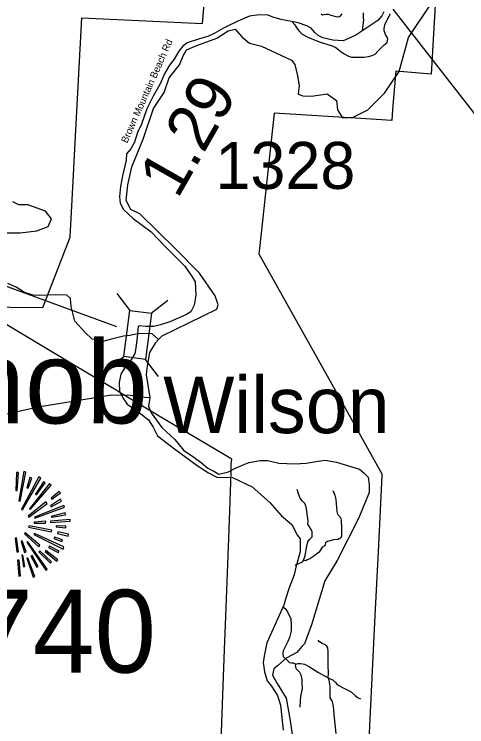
# Model space of a CAD drawing. Extents: x 1159738 to 1321356, y 736314 to 882035.
# Drawn here: x 1180449 to 1185260, y 816118 to 823694 of the extents above; entities that cross this region are included whole.
import ezdxf

# ---------------------------------------------------------------- set-up
doc = ezdxf.new("R2010")
doc.units = 0
for name, color, linetype in [('Exist Boundary Land Use Forest National US Forest Service', 7, 'Continuous'), ('Exist Geographical Mountain Summit CELL', 7, 'Continuous'), ('Exist Geographical Mountain Summit Elevation Number Label', 7, 'Continuous'), ('Exist Geographical Mountain Summit Label', 7, 'Continuous'), ('Exist Hydrographic Creek Single Shore', 7, 'Continuous'), ('Exist Hydrographic Creek Single Shore Label', 7, 'Continuous'), ('Exist Road Non-System Type 51', 7, 'Continuous'), ('Exist Road Secondary Mileage Hundredths English Label', 7, 'Continuous'), ('Exist Road Secondary Structure Standard Bridge CELL', 7, 'Continuous'), ('Exist Road Secondary Structure Standard Bridge Number Label', 7, 'Continuous'), ('Exist Road Secondary Type 41 Attributed', 7, 'Continuous'), ('Exist Road Secondary Type 51 Label', 7, 'Continuous'), ('Exist Road Secondary Type 51 Number Label', 7, 'Continuous')]:
    doc.layers.add(name, color=color, linetype=linetype)

msp = doc.modelspace()

# ---------------------------------------------------------------- linework, layer by layer
at = {"layer": 'Exist Boundary Land Use Forest National US Forest Service'}
for points in [[(1181077.2, 821985.4), (1181096, 822331.8), (1181167.4, 823654.7), (1182450.4, 823595.7), (1182625.4, 825621.8), (1181994.3, 825639.1), (1181234.4, 825659.8), (1181255.3, 826054.8), (1181338.3, 827288.9), (1181518.2, 827293.9), (1181553.8, 828399.8), (1181557.3, 828511.9), (1181490.6, 828516.2), (1181211.2, 828534.3), (1180846.2, 828557.9), (1180845.6, 828555), (1180799.3, 828350.9), (1180737.3, 828248.9), (1180670.2, 828186.9), (1180611.3, 828143.9), (1180560.2, 828127.9), (1180461.3, 828103.9), (1180360.3, 828086.9)], [(1184945.2, 824175.1), (1184917, 823671.3), (1184882.5, 823056.8), (1184504.5, 823087.8), (1184471.8, 822681), (1184462.5, 822564.7), (1184077.2, 822588.5), (1184012.8, 822592.5), (1183957.3, 822595.9), (1183213.5, 822641.7), (1183054.5, 821201.7), (1183047.5, 821147.7), (1183972.5, 819495.7), (1184187.7, 819111.4), (1184357.7, 818807.6), (1184356.6, 818788), (1184316.2, 817978), (1184282.6, 817301.6), (1184211.7, 815834.6)], [(1182508.3, 815466.3), (1182522.7, 815466.5), (1182640.7, 815773.5), (1182683.7, 816938.3), (1182693.7, 817202.6), (1182732, 818216.6), (1182751, 818718.3), (1182755.5, 818839.6), (1182753.5, 818911.6), (1182761.5, 818961.6), (1181970.5, 819431.6), (1181864.5, 819494.6), (1181563.8, 819677.1), (1181538, 819692.8), (1181497.4, 819717.4), (1181490.5, 819721.6), (1181079, 819966.9), (1180046.5, 820582.6), (1180752.5, 820574.6), (1180798.9, 820694.6), (1181041.5, 821322.7), (1181077.2, 821985.4)]]:
    msp.add_lwpolyline(points, dxfattribs=at)
at = {"layer": 'Exist Geographical Mountain Summit CELL'}
for points in [[(1180464, 818631.8), (1180479.7, 818631.8), (1180494.3, 818820.7), (1180472.5, 818820.7)], [(1180511.9, 818518.2), (1180571.5, 818826.4), (1180549.6, 818833.6), (1180498.8, 818521.2)], [(1180524.9, 818431.1), (1180536.6, 818423.8), (1180731.2, 818762.3), (1180709.4, 818777.1)], [(1180582.9, 818659.2), (1180596.2, 818654.7), (1180634, 818762.3), (1180615.1, 818769.5)], [(1180609.1, 818436.8), (1180618, 818428.2), (1180840.3, 818685.3), (1180824.3, 818704.3)], [(1180758.9, 818723.3), (1180674.7, 818589.5), (1180686.4, 818585), (1180776.2, 818710.3)], [(1180840.3, 818548.8), (1180847.7, 818538.7), (1180939.2, 818603.9), (1180924.6, 818618.5)], [(1180840.3, 818457.3), (1180950.7, 818516.9), (1180939.2, 818537.1), (1180834.7, 818467.4)], [(1180596.2, 818356.9), (1180603.4, 818346.8), (1180798, 818490.6), (1180785.2, 818508.1)], [(1180664.3, 818345.3), (1180668.7, 818336.4), (1180981.3, 818451.2), (1180974.1, 818470.1)], [(1180847.7, 818345.3), (1180994.6, 818371.5), (1180988.7, 818393.2), (1180841.9, 818354.2)], [(1180660.3, 818294.6), (1180660.3, 818282.9), (1180780.7, 818282.9), (1180783.6, 818303.1)], [(1180833.1, 818290.1), (1181042.5, 818303.1), (1181043.8, 818322), (1180834.7, 818303.1)], [(1180601.8, 818239.3), (1180844.8, 818191.4), (1180849.1, 818208.7), (1180606.3, 818253.7)], [(1180892.7, 818242.2), (1180998.7, 818233.2), (1180998.7, 818250.7), (1180894.3, 818255)], [(1180557.1, 818170.9), (1180711, 818029.8), (1180721.1, 818047.2), (1180564.3, 818179.7)], [(1180657, 818160.8), (1180969.8, 818008), (1180977, 818029.8), (1180663.1, 818172.3)], [(1180870.9, 818120.1), (1180955.2, 818087.9), (1180962.4, 818105.5), (1180876.7, 818132.9)], [(1180908.9, 818173.6), (1181022, 818144.6), (1181024.9, 818166.4), (1180912.9, 818191.4)], [(1180459.5, 818124.4), (1180475.4, 817976.3), (1180493, 817977.4), (1180472.5, 818127.3)], [(1180523.6, 818089.5), (1180558.4, 817970.2), (1180574.4, 817977.4), (1180532.1, 818093.8)], [(1180581.6, 818080.5), (1180783.6, 817781.3), (1180798, 817792.8), (1180591.7, 818085)], [(1180711, 817977.4), (1180831.5, 817861.1), (1180844.8, 817871.5), (1180719.8, 817987.5)], [(1180777.8, 817980.3), (1180899.9, 817877.1), (1180912.9, 817891.7), (1180785.2, 817990.7)], [(1180814.2, 818024.2), (1180914.5, 817971.8), (1180924.6, 817986.3), (1180823, 818039.9)], [(1180562.7, 817823.4), (1180540.9, 817942.8), (1180527.8, 817942.8), (1180545.4, 817819.1)], [(1180581.6, 817909.3), (1180651.4, 817710), (1180668.7, 817717.2), (1180593.3, 817912.2)], [(1180623.6, 817932.4), (1180687.6, 817814.6), (1180703.8, 817823.4), (1180638.5, 817938.3)], [(1180484.2, 817890.4), (1180498.8, 817720.4), (1180514.8, 817724.4), (1180501.5, 817890.4)]]:
    msp.add_lwpolyline(points, close=True, dxfattribs=at)
at = {"layer": 'Exist Hydrographic Creek Single Shore'}
for points in [[(1181983.1, 820235), (1182020.2, 820275), (1182601.5, 820558.9), (1182616.9, 820602.5), (1182583.6, 820699.9), (1182419.6, 820940.9), (1182164.4, 821201), (1181782.2, 821570.3), (1181687.4, 821619), (1181638.7, 821713.8), (1181656.6, 821879.6), (1181697.5, 822071.9), (1181820.5, 822366.7), (1181930, 822691.2), (1182042.7, 822860.4), (1182094, 823019.3), (1182206.7, 823157.8), (1182245.1, 823250.1), (1182281, 823316.7), (1182388.6, 823362.9), (1182601.2, 823439.8), (1182721.6, 823519.2), (1182798.5, 823534.6), (1182872.8, 823450), (1182949.6, 823385.9), (1183077.7, 823355.2), (1183395, 823206.7), (1183430.8, 823158), (1183461.6, 823040.1), (1183479.5, 822937.5), (1183466.7, 822845.2), (1183515.4, 822827.3), (1183610.2, 822822.2), (1183776.7, 822847.8), (1183874.1, 822778.6), (1183884.3, 822676), (1183938.1, 822594), (1184050.8, 822599.1), (1184209.7, 822676), (1184383.9, 822855.5), (1184542.7, 823086.2), (1184640.4, 823447.1), (1184884.4, 823813.2)], [(1180362.1, 821368.9), (1180513.2, 821368.9), (1180687.4, 821391.9), (1180810.4, 821435.5), (1180843.7, 821520.1), (1180782.2, 821599.6), (1180592.6, 821666.3), (1180496.3, 821667.7), (1180432.2, 821701)], [(1181759.3, 820296.1), (1181677.9, 820279.1), (1181611.1, 820270.1), (1181467.7, 820236.8), (1181401.1, 820216.3), (1181275.5, 820239.4), (1181203.8, 820308.6), (1181091.1, 820431.6), (1181055.2, 820588), (1181047.5, 820670.1), (1181006.5, 820708.5), (1180886.1, 820711.1), (1180722.2, 820703.4), (1180650.4, 820708.5), (1180558.2, 820734.2), (1180468.5, 820790.6), (1180378.9, 820831.6)], [(1181983.1, 820235), (1181913.6, 820294.4), (1181854.5, 820300.9), (1181759.3, 820296.1)], [(1181983.1, 820235), (1181948, 820198.3), (1181886.5, 820095.7), (1181868.6, 819993.2), (1181858.4, 819931.6), (1181850.7, 819859.9), (1181889.1, 819618.9)], [(1180306.6, 819430.5), (1180701.5, 819521.2), (1181157.3, 819593.9), (1181354.5, 819626.2), (1181480.1, 819647.8), (1181682.5, 819642.6), (1181779.8, 819624.7), (1181889.1, 819618.9)], [(1181889.1, 819618.9), (1181875.4, 819524.8), (1181903.6, 819455.5), (1182018.9, 819299.2), (1182154.6, 819173.5), (1182246.9, 819060.7), (1182359.6, 818983.8), (1182439, 818924.9), (1182508.2, 818868.5), (1182569.7, 818835.1), (1182623.5, 818804.4), (1182725.9, 818830), (1182807.9, 818871), (1182941.2, 818927.4), (1183061.6, 818947.9), (1183141, 818947.9), (1183261.4, 818919.7), (1183433, 818914.6), (1183553.4, 818919.7), (1183679, 818942.8), (1183753.3, 818953.1), (1183876.2, 818932.6), (1184119.6, 818858.2), (1184164.8, 818817.9), (1184210.9, 818771.7), (1184223.7, 818692.2), (1184221.2, 818607.6), (1184111, 818341), (1183880.5, 817885.8), (1183752.4, 817670.5), (1183609.1, 817200.1), (1183534.8, 817000.1), (1183506.7, 816971.9), (1183452.9, 816907.8), (1183340.1, 816848.8), (1183248.5, 816765.6), (1183210.1, 816732.3), (1183194.7, 816668.2), (1183243.4, 816578.5), (1183340.8, 816422.1), (1183381.8, 816186.2), (1183404.8, 816035)]]:
    msp.add_lwpolyline(points, dxfattribs=at)
at = {"layer": 'Exist Road Non-System Type 51'}
for points in [[(1183404.5, 823614.1), (1183431.2, 823579.8), (1183461.7, 823534), (1183486.5, 823505.3), (1183509.4, 823482.4), (1183568.5, 823451.9), (1183702, 823398.5), (1183818.3, 823360.3), (1183866, 823339.3), (1183921.3, 823297.4), (1183955.6, 823272.5), (1184001.4, 823249.6), (1184035.7, 823236.3), (1184100.5, 823238.2), (1184167.3, 823238.2), (1184216.8, 823243.9), (1184255, 823255.4), (1184287.4, 823270.6), (1184316, 823301.2), (1184352.2, 823341.2), (1184382.7, 823368), (1184413.2, 823394.7), (1184417.1, 823411.8), (1184419, 823436.6), (1184394.2, 823478.6), (1184382.7, 823516.8), (1184380.8, 823543.5), (1184390.4, 823579.8), (1184419, 823648.5), (1184449.5, 823700)], [(1183710.4, 823698.2), (1183725.8, 823688.7), (1183740.7, 823691.1), (1183766.3, 823695.9), (1183787.1, 823693.5), (1183813.3, 823685.1), (1183866.3, 823669.7), (1183887.7, 823667.3), (1183905.5, 823669.7), (1183917.7, 823676.2), (1183936.2, 823697.6)], [(1184158, 823709.8), (1184157.4, 823685.4), (1184159.8, 823656.8), (1184163.4, 823632.4), (1184150.3, 823549), (1184149.1, 823517.7)], [(1183436.4, 817835.2), (1183468.7, 817850.6), (1183511.8, 817872.2), (1183524.1, 817884.5), (1183533.3, 817918.3), (1183541, 817939.8), (1183559.4, 818039.8), (1183570.2, 818084.5), (1183587.1, 818110.6), (1183599.4, 818121.4), (1183614.8, 818136.8), (1183617.8, 818153.7), (1183617.8, 818190.6), (1183605.5, 818216.7), (1183588.6, 818244.4), (1183571.7, 818272.1), (1183573.2, 818309.1), (1183551.7, 818456.7), (1183536.4, 818490.6), (1183511.8, 818515.2), (1183488.7, 818547.5), (1183471.8, 818593.6), (1183456.4, 818639.8)], [(1183834.7, 818628.4), (1183857.8, 818579.1), (1183868.6, 818533), (1183877.8, 818405.3), (1183887, 818377.6), (1183917.8, 818343.8), (1183923.9, 818313), (1183928.5, 818225.3), (1183926.9, 818141.2), (1183919.2, 818130.5), (1183910, 818118.2), (1183891.5, 818107.4), (1183846.9, 818104.3), (1183780.8, 818088.9), (1183756.2, 818072), (1183751.6, 818042.8), (1183724, 818025.9), (1183711.7, 818008.9), (1183691.7, 817973.6), (1183633.3, 817932), (1183590.4, 817904.7), (1183562.7, 817892.4), (1183547.3, 817881.6), (1183524.1, 817884.5)], [(1183303, 817392.3), (1183327.6, 817376.9), (1183353.7, 817341.5), (1183389.1, 817264.6), (1183393.7, 817198.4), (1183393.7, 817138.4), (1183375.3, 817067.7), (1183356.8, 817024.6), (1183307.6, 816924.6), (1183303, 816898.5), (1183309.2, 816866.1), (1183350.7, 816824.6), (1183375.2, 816801.9), (1183396.7, 816797.3), (1183415.2, 816797.3), (1183444.4, 816783.4)], [(1183787, 816638), (1183788.6, 816687.3), (1183785.5, 816773.4), (1183785.5, 816914.9), (1183782.4, 816956.5), (1183773.2, 816974.9), (1183754.7, 816990.3), (1183722.5, 817004.2), (1183693.2, 817019.6), (1183679.4, 817038)], [(1183444.4, 816783.4), (1183436.5, 816774.5), (1183438, 816757.6), (1183444.2, 816737.6), (1183482.6, 816699.1), (1183494.9, 816668.3), (1183507.2, 816622.2), (1183505.7, 816576), (1183510.3, 816526.8), (1183501.1, 816489.9), (1183490.3, 816444.2), (1183487.2, 816393.4), (1183485.7, 816325.8)], [(1183444.4, 816783.4), (1183464.2, 816788.8), (1183494.9, 816788.8), (1183534.9, 816784.2), (1183587.2, 816756.5), (1183684, 816696.5), (1183787, 816638), (1183840.8, 816611.9), (1183862.3, 816593.4), (1183886.9, 816564.2), (1183960.7, 816525.7), (1184029.9, 816490.4), (1184072.9, 816451.9), (1184105.2, 816424.2), (1184128.3, 816413.4)], [(1183787, 816638), (1183798, 816593.7), (1183804.2, 816549.1), (1183802.6, 816506.1), (1183804.2, 816449.1), (1183805.7, 816426.1), (1183828.8, 816386.1), (1183838, 816333.8), (1183848.8, 816212.2), (1183867.2, 816047.6)]]:
    msp.add_lwpolyline(points, dxfattribs=at)
at = {"layer": 'Exist Road Secondary Structure Standard Bridge CELL'}
for p, q in [((1181679.4, 820544.8), (1181541.3, 820724.2)), ((1181903.8, 820515.6), (1182083.2, 820653.6)), ((1181434.8, 819915.3), (1181614.2, 820053.4)), ((1181981.9, 819844), (1181843.9, 820023.4))]:
    msp.add_line(p, q, dxfattribs=at)
msp.add_lwpolyline([(1181614.2, 820053.4), (1181678.3, 820545), (1181908, 820515.1), (1181843.9, 820023.4)], close=True, dxfattribs=at)
at = {"layer": 'Exist Road Secondary Structure Standard Bridge Number Label'}
for p, q in [((1184475.5, 823749), (1186641.8, 820957.8)), ((1181540.9, 820369), (1172676, 823613.2))]:
    msp.add_line(p, q, dxfattribs=at)
at = {"layer": 'Exist Road Secondary Type 41 Attributed'}
for points in [[(1184377.7, 823720.2), (1184357.7, 823677.4), (1184314.9, 823628.7), (1184209.2, 823557.3), (1184081.5, 823471.9), (1184001.5, 823434.8), (1183944.3, 823410.5), (1183834.3, 823419), (1183730, 823444.8), (1183680, 823469.1), (1183642.9, 823500.5), (1183604.3, 823547.7), (1183560, 823572), (1183467.2, 823603.5), (1183287.2, 823637.8), (1183197.2, 823662.1), (1183148, 823683.2), (1183053.8, 823688.9), (1182950.9, 823674.6), (1182825.2, 823621.7), (1182700, 823559.1)], [(1182700, 823559.1), (1182673.7, 823545.9), (1182575.2, 823490.2), (1182508, 823457.3), (1182416.6, 823433), (1182286.1, 823389.6), (1182240.4, 823353.9), (1182197.6, 823302.4), (1182147.6, 823215.2), (1182100.4, 823152.3), (1182050.4, 823068), (1181997.6, 822947.9), (1181926.5, 822823), (1181857.9, 822688.6), (1181800.7, 822524.2), (1181760.7, 822438.4), (1181726.5, 822332.6), (1181689.3, 822264), (1181643.6, 822209.7), (1181637.9, 822143.9), (1181597.9, 821975.2), (1181577.9, 821860.9), (1181566.5, 821756.9), (1181575.1, 821685.4), (1181609.4, 821616.8), (1181712.2, 821522.4), (1181903.7, 821379.5), (1182055.1, 821222.2), (1182263.7, 821016.3), (1182340.8, 820902), (1182372.3, 820850.5), (1182378, 820707.5), (1182360.6, 820600.4), (1182326.3, 820528.9), (1182280.6, 820503.2), (1182103.5, 820423.2), (1182003.5, 820391.7), (1181932, 820374.5), (1181849.2, 820374.5), (1181780.1, 820381.2), (1181766.2, 820372.9), (1181761.6, 820343.3), (1181759.3, 820296.1)], [(1181759.3, 820296.1), (1181753.3, 820229.5), (1181742, 820148.7), (1181730.6, 820085.8), (1181696.3, 820025.7), (1181630.6, 819948.5), (1181582, 819865.6), (1181563.7, 819776.9), (1181568.4, 819682.1), (1181610.6, 819605.4), (1181649.6, 819549.1), (1181762, 819469.5), (1181876.3, 819380.9), (1181924.7, 819304.9), (1181970.6, 819213.1), (1182153.5, 819072.1), (1182392.8, 818894.6), (1182512.2, 818818.1), (1182600.9, 818772.2), (1182769.2, 818769.1), (1182978.2, 818669.1), (1183166.6, 818504.1), (1183289.7, 818361.4), (1183401.2, 818269.5), (1183461.2, 818152.3), (1183488.5, 818114.5), (1183489.6, 817977.1), (1183443.9, 817814.1), (1183423.9, 817734.1), (1183372.5, 817593.9), (1183332.5, 817473.9), (1183315.4, 817412.3), (1183135.4, 817009.2), (1183106.8, 816869.1), (1183095.4, 816800.4), (1183109.6, 816703.2), (1183138.2, 816606), (1183183.9, 816548.8), (1183246.8, 816448.7), (1183278.2, 816348.7), (1183292.5, 816217.1), (1183309.5, 816082.6)]]:
    msp.add_lwpolyline(points, dxfattribs=at)

# ---------------------------------------------------------------- texts
at = {"layer": 'Exist Geographical Mountain Summit Elevation Number Label'}
msp.add_text('Elevation 1740', height=880, dxfattribs=at).set_placement((1174170.5, 816693.9))
at = {"layer": 'Exist Geographical Mountain Summit Label'}
msp.add_text('Woodcock Knob', height=880, dxfattribs=at).set_placement((1173302.1, 819343.6))
at = {"layer": 'Exist Hydrographic Creek Single Shore Label'}
msp.add_text('Wilson', height=600, dxfattribs=at).set_placement((1182032.5, 819239.8))
at = {"layer": 'Exist Road Secondary Mileage Hundredths English Label'}
msp.add_text('1.29', height=500, rotation=60.34376, dxfattribs=at).set_placement((1182184.9, 821720.9))
at = {"layer": 'Exist Road Secondary Type 51 Label'}
msp.add_text('Brown Mountain Beach Rd', height=75, rotation=65.98076, dxfattribs=at).set_placement((1181649.3, 822317.8))
at = {"layer": 'Exist Road Secondary Type 51 Number Label'}
msp.add_text('1328', height=500, dxfattribs=at).set_placement((1182587.7, 821836.9))

doc.saveas('drawing.dxf')
